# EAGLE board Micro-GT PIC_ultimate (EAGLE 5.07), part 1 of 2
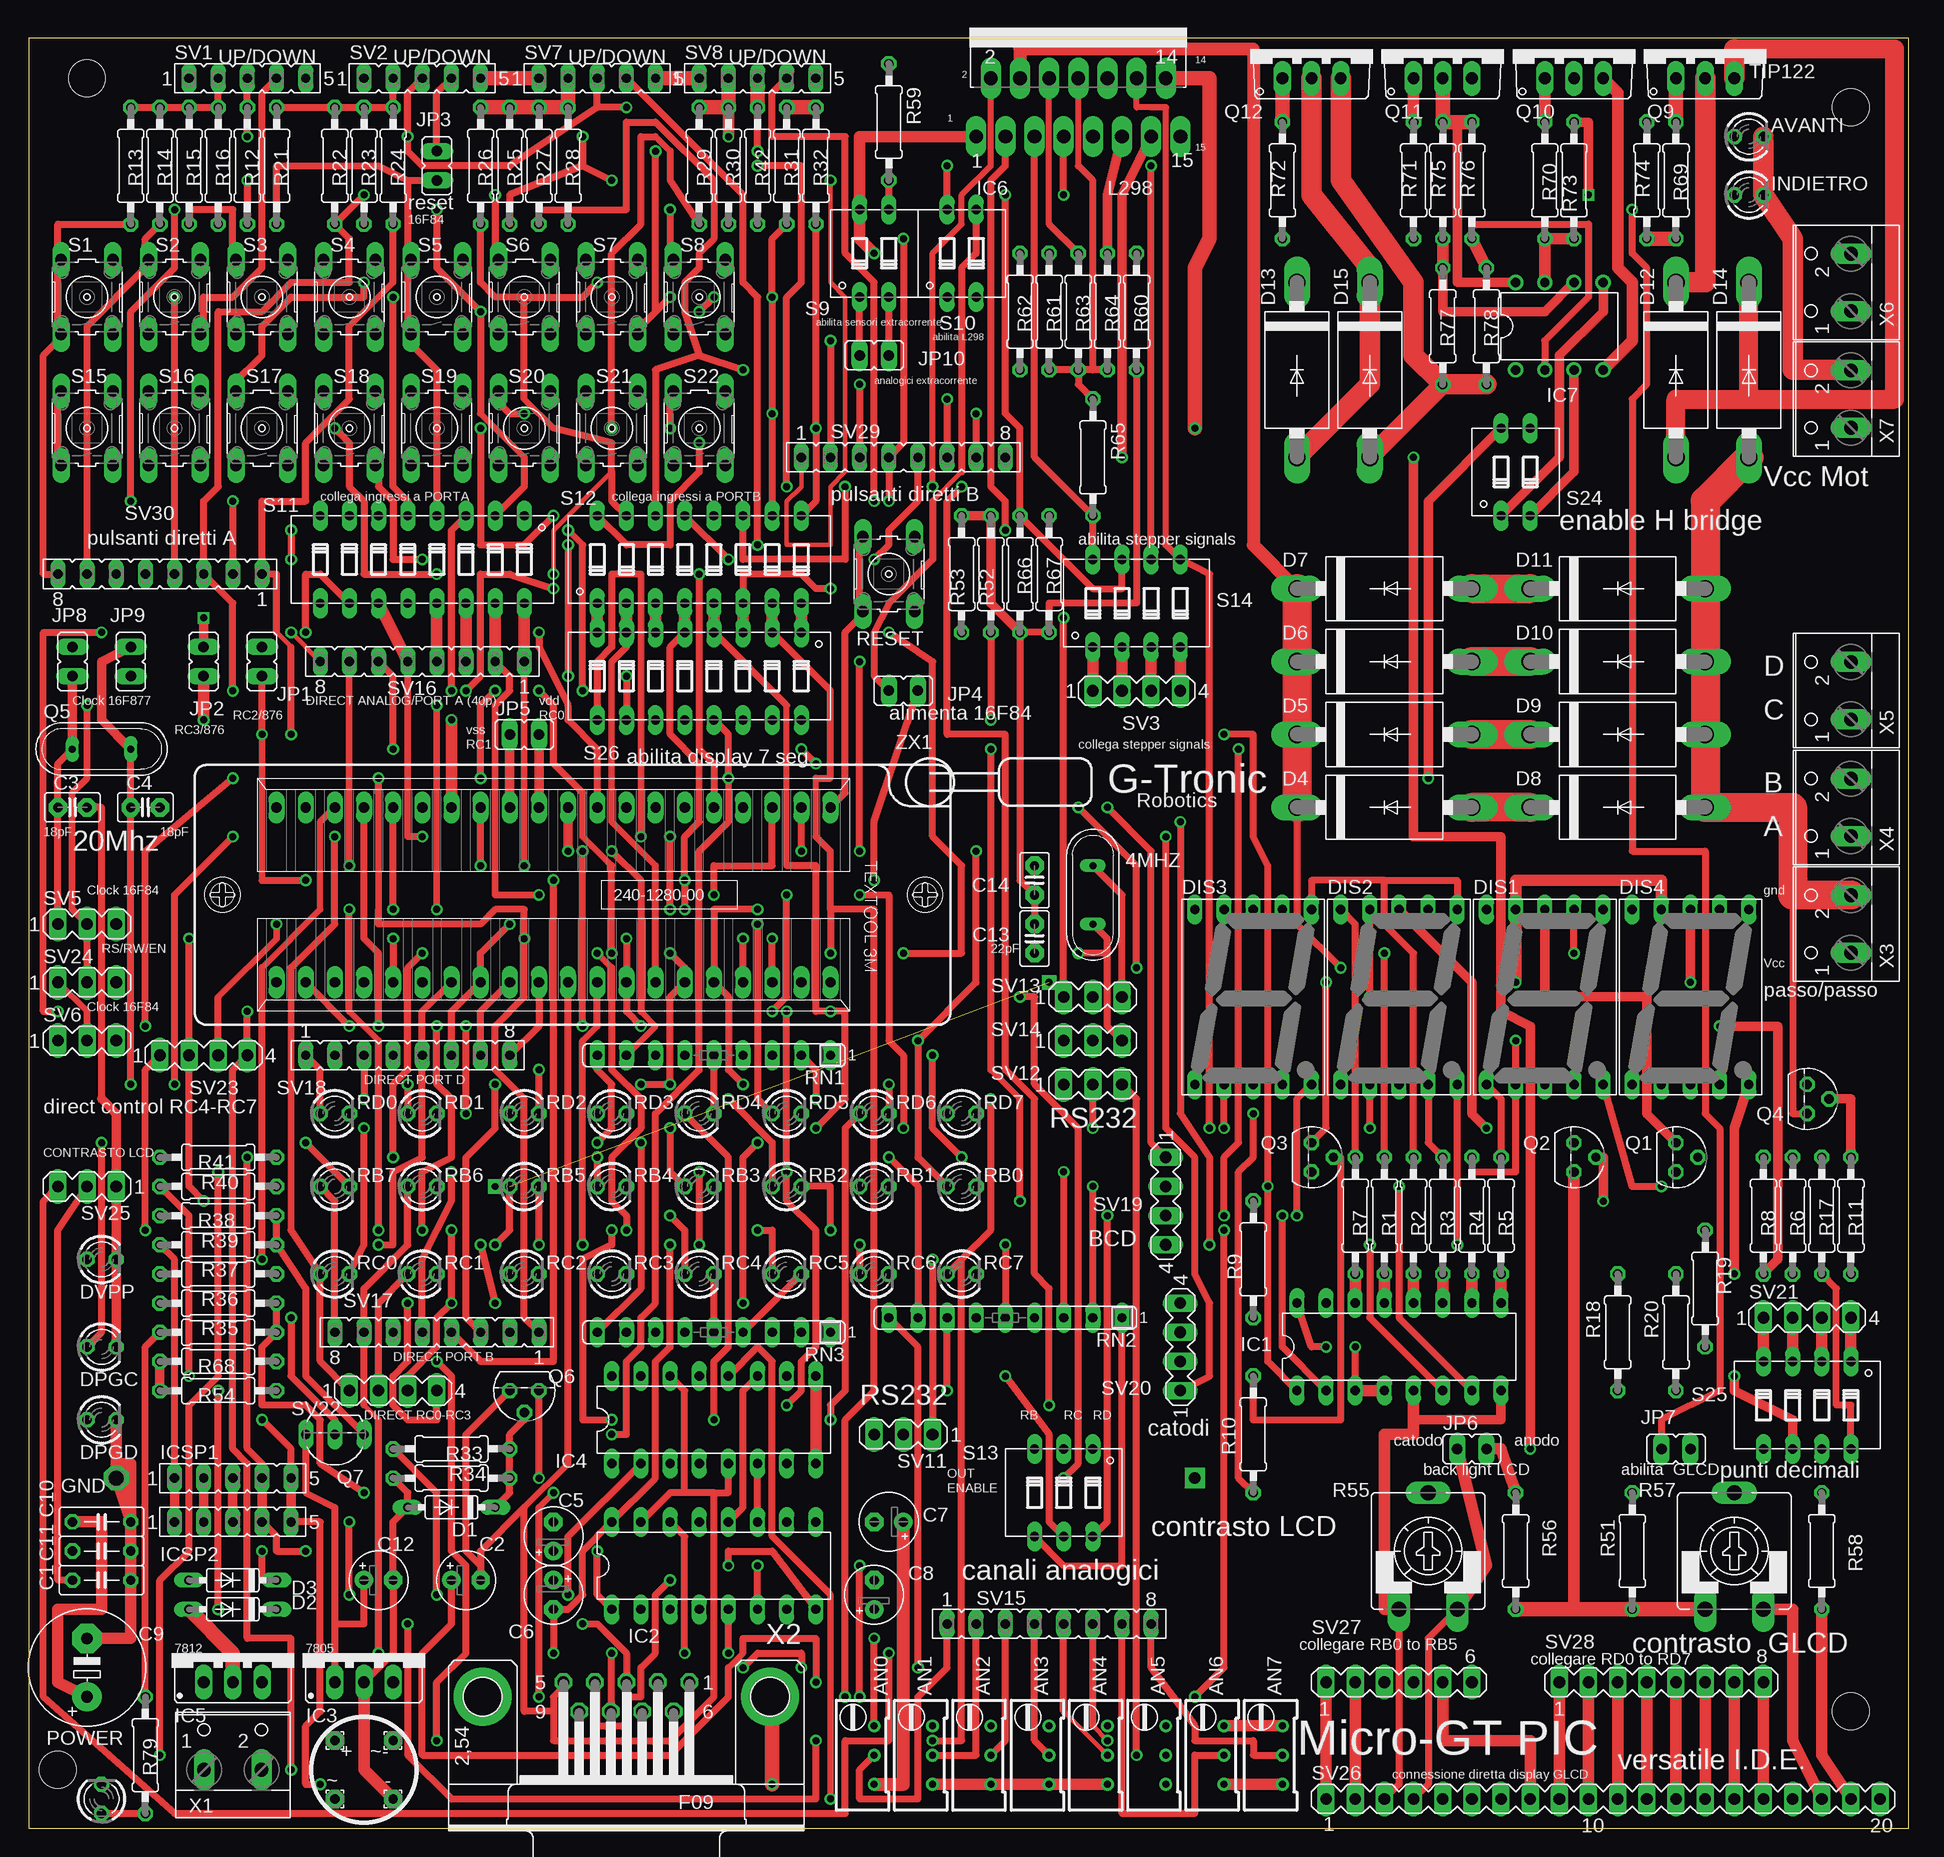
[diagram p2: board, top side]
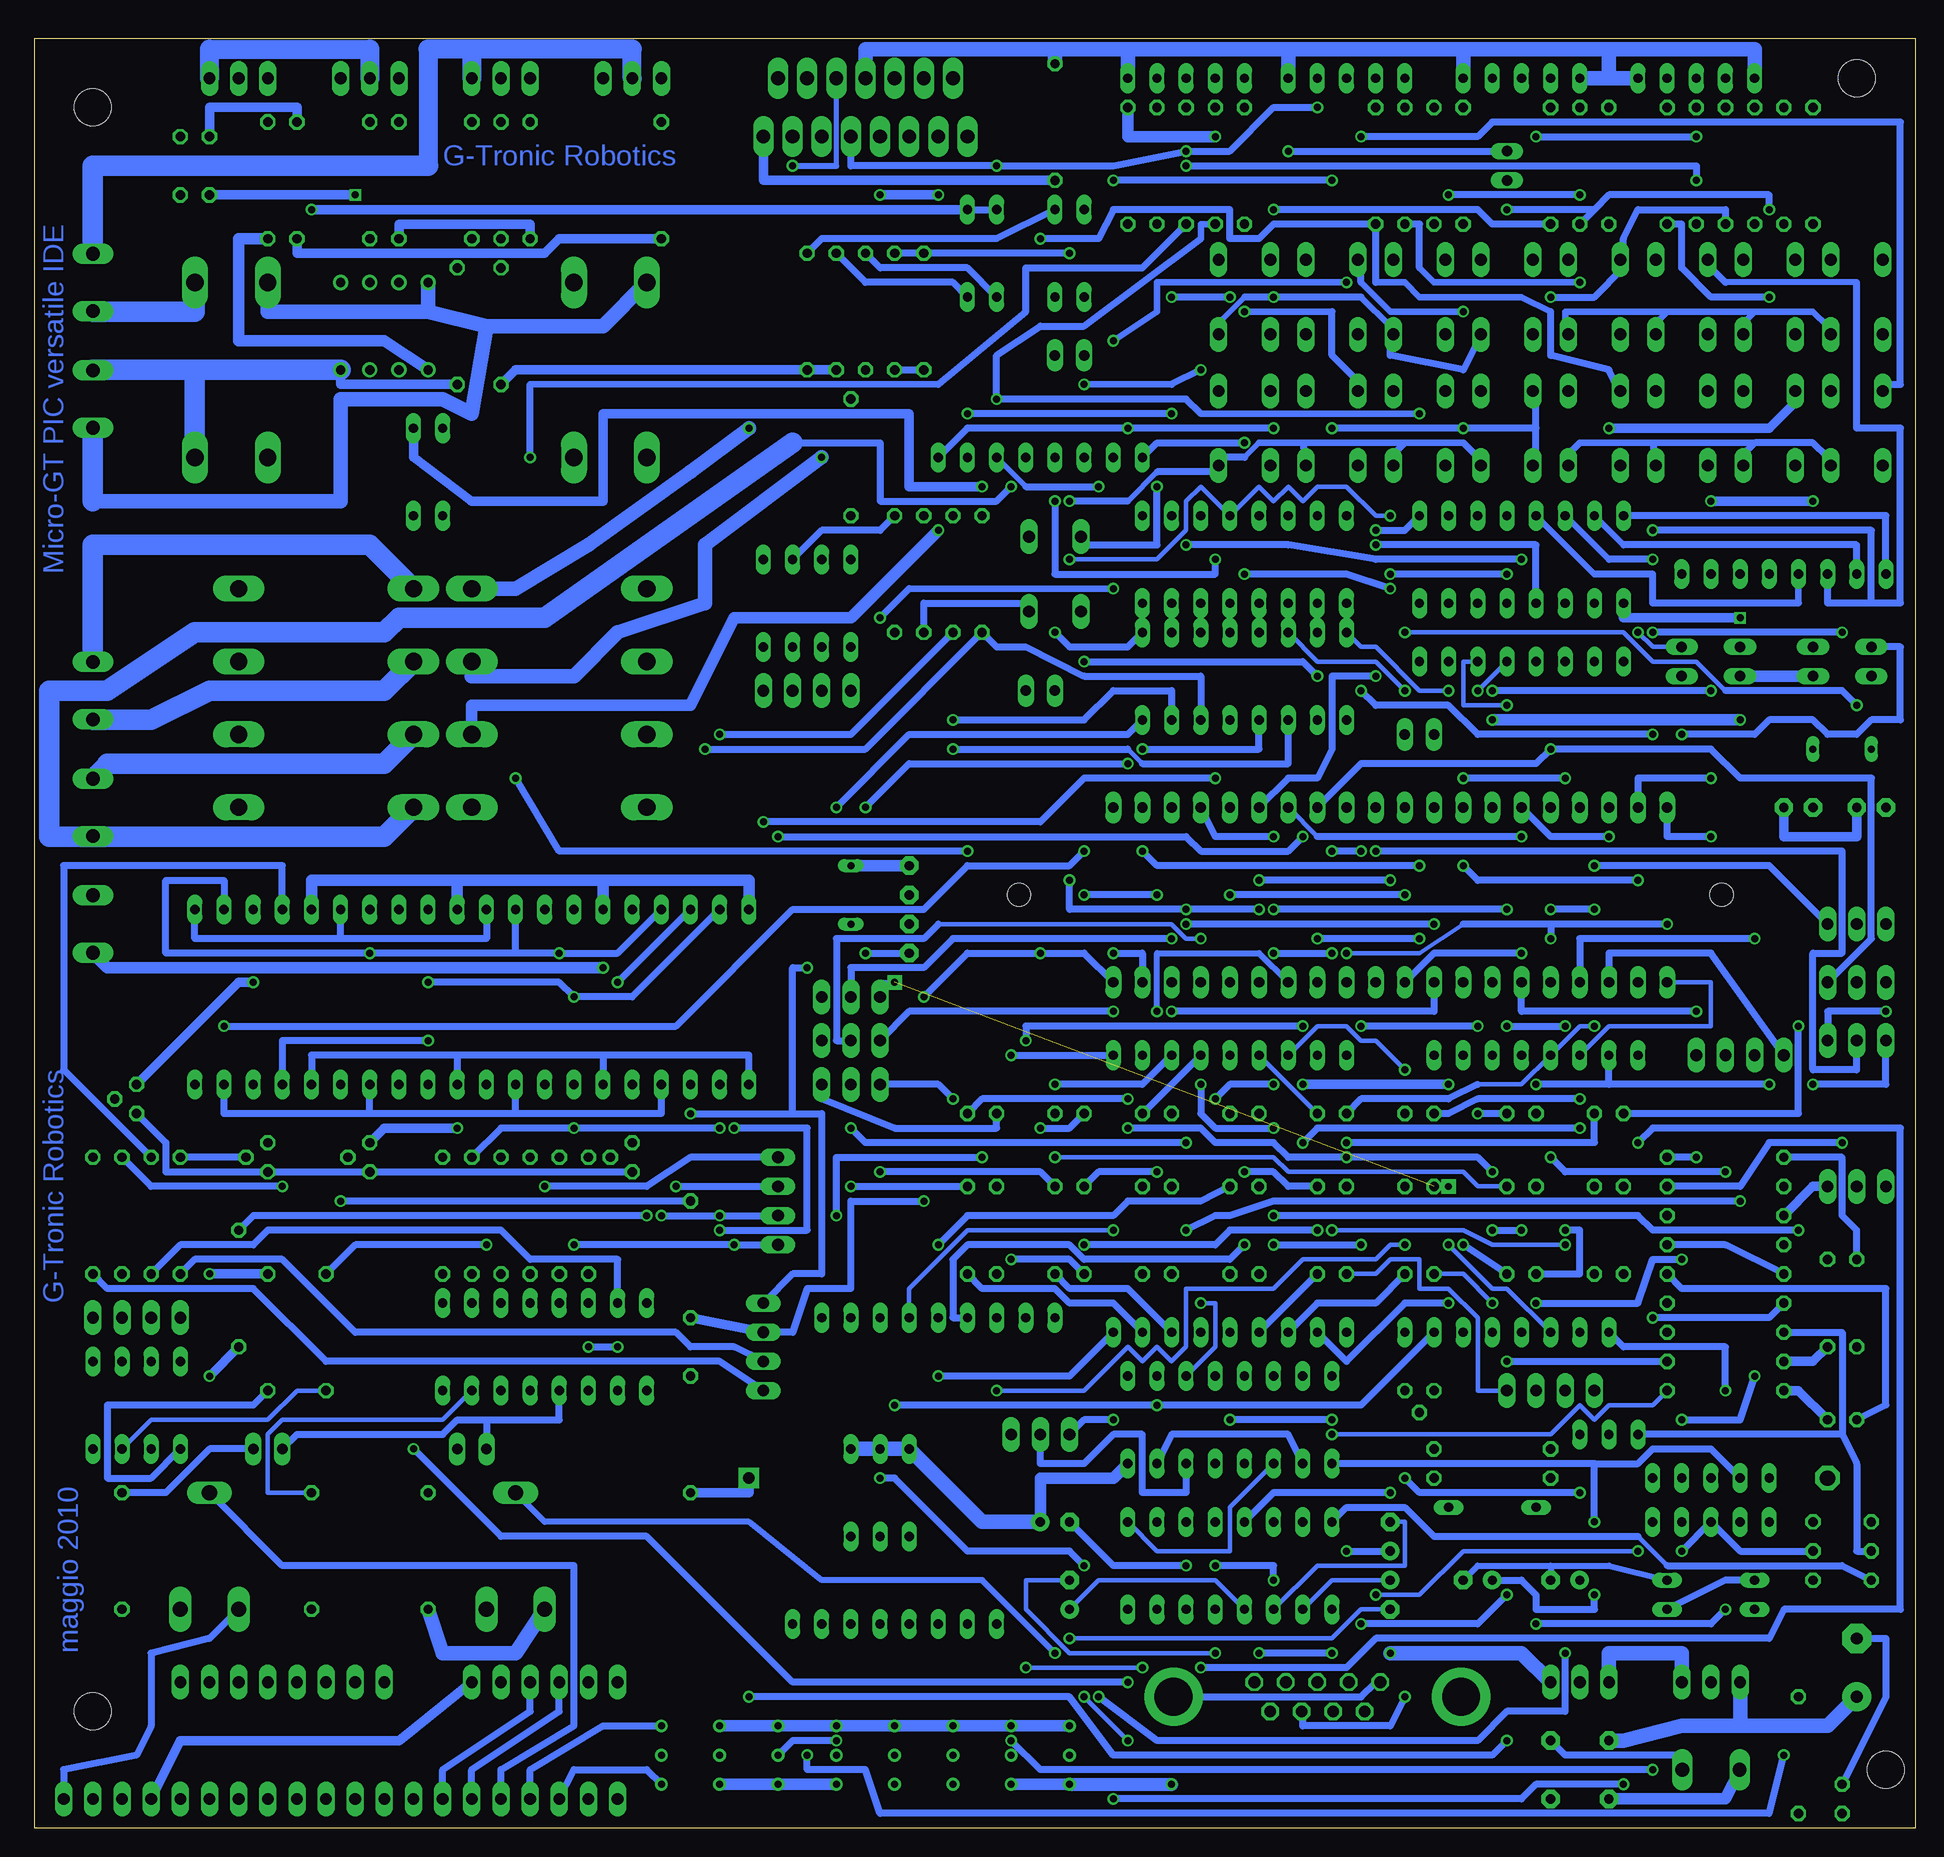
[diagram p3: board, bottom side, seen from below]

Size 163.81 x 155.88 mm. Coordinates in mm from the lower left corner, seen from the top.
Outline: 0,0 163.81,0 163.81,155.88 0,155.88 0,0
Copper layers (1*16): Top 0.035mm / dielectric 1.5mm / Bottom 0.035mm
Design rules "default": minimum track width 10mil, minimum drill 24mil, track to track 8mil, track to pad 8mil, pad to pad 8mil, via to via 8mil, smd to smd 8mil, copper to edge 40mil, drill to drill 8mil, minimum pad ring 10mil, minimum via ring 8mil, stop-mask expansion 4mil, vias tented up to drill 0mil, thermal gap 10mil
Holes 3.2 mm at 158.75,149.86 158.75,10.16 2.54,5.08 5.08,152.4

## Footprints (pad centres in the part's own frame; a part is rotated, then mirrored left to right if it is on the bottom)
QS = drill 0.61 long: 1 -2.54,0; 2 2.54,0
1,6/0,8 = drill 0.813 pad 1.6 octagon: 1 0,0
RTRIM64W = drill 0.61 round: 1 1.27,-2.54; 2 1.27,0; 3 1.27,2.54
LED3MM = drill 0.813 octagon: A -1.27,0; K 1.27,0
C050-025X075 = drill 0.813 octagon: 1 -2.54,0; 2 2.54,0
E2,5-5 = drill 0.813 pad 1.6 round: + -1.27,0 | drill 0.813 pad 1.6 octagon: - 1.27,0
C2.5-2 = drill 0.813 pad 1.6 octagon: 1 -1.27,0; 2 1.27,0
E5-10,5 = drill 1.016 pad 2.54 round: + -2.54,0 | drill 1.016 pad 2.54 octagon: - 2.54,0
DO35-7 = drill 0.813 long: A 3.81,0; C -3.81,0
DO201-15 = drill 1.499 long: A 7.62,0; C -7.62,0
HDSP-M = drill 0.813 long: 1 -5.08,-7.62; 2 -2.54,-7.62; 3 0,-7.62; 4 2.54,-7.62; 5 5.08,-7.62; 6 5.08,7.62; 7 2.54,7.62; 8 0,7.62; 9 -2.54,7.62; 10 -5.08,7.62
P1-13 = drill 1.321 pad 2.159 octagon: TP 0,0
DIL16 = drill 0.813 long: 1 -8.89,-3.81; 2 -6.35,-3.81; 3 -3.81,-3.81; 4 -1.27,-3.81; 5 1.27,-3.81; 6 3.81,-3.81; 7 6.35,-3.81; 8 8.89,-3.81; 9 8.89,3.81; 10 6.35,3.81; 11 3.81,3.81; 12 1.27,3.81; 13 -1.27,3.81; 14 -3.81,3.81; 15 -6.35,3.81; 16 -8.89,3.81
78XXS = drill 1.016 long: GND 0,-2.54; IN -2.54,-2.54; OUT 2.54,-2.54
MULTIWATT-15 = drill 1.2 long: 1 -8.89,-7.62; 2 -7.62,-2.54; 3 -6.35,-7.62; 4 -5.08,-2.54; 5 -3.81,-7.62; 6 -2.54,-2.54; 7 -1.27,-7.62; 8 0,-2.54; 9 1.27,-7.62; 10 2.54,-2.54; 11 3.81,-7.62; 12 5.08,-2.54; 13 6.35,-7.62; 14 7.62,-2.54; 15 8.89,-7.62
DIL08 = drill 0.813 pad 1.27 round: 1 -3.81,-3.81; 2 -1.27,-3.81; 3 1.27,-3.81; 4 3.81,-3.81; 5 3.81,3.81; 6 1.27,3.81; 7 -1.27,3.81; 8 -3.81,3.81
FE05-1 = drill 0.813 long: 1 -5.08,0; 2 -2.54,0; 3 0,0; 4 2.54,0; 5 5.08,0
JP1 = drill 0.914 long: 1 0,-1.27; 2 0,1.27
TO92 = drill 0.813 octagon: 1 1.27,0; 2 0,1.905; 3 -1.27,0
TO92-EBC = drill 0.813 long: B 0,-1.27; C -2.54,-1.27; E 2.54,-1.27
TO220AV = drill 1.016 long: B -2.54,-2.54; C 0,-2.54; E 2.54,-2.54
0207/10 = drill 0.813 octagon: 1 -5.08,0; 2 5.08,0
CA9V = drill 1.321 long: A -2.54,-5.08; E 2.54,-5.08; S 0,5.08
B3F-10XX = drill 1.016 long: 1 -3.251,2.261; 2 3.251,2.261; 3 -3.251,-2.261; 4 3.251,-2.261
SIL9 = drill 0.813 long: 1 -10.16,0; 2 -7.62,0; 3 -5.08,0; 4 -2.54,0; 5 0,0; 6 2.54,0; 7 5.08,0; 8 7.62,0; 9 10.16,0
DIP02YL = drill 0.813 long: 1 -1.27,-3.81; 2 1.27,-3.81; 3 1.27,3.81; 4 -1.27,3.81
DIP08YL = drill 0.813 long: 1 -8.89,-3.81; 2 -6.35,-3.81; 3 -3.81,-3.81; 4 -1.27,-3.81; 5 1.27,-3.81; 6 3.81,-3.81; 7 6.35,-3.81; 8 8.89,-3.81; 9 8.89,3.81; 10 6.35,3.81; 11 3.81,3.81; 12 1.27,3.81; 13 -1.27,3.81; 14 -3.81,3.81; 15 -6.35,3.81; 16 -8.89,3.81
DIP03YL = drill 0.813 long: 1 -2.54,-3.81; 2 0,-3.81; 3 2.54,-3.81; 4 2.54,3.81; 5 0,3.81; 6 -2.54,3.81
DIP04YL = drill 0.813 long: 1 -3.81,-3.81; 2 -1.27,-3.81; 3 1.27,-3.81; 4 3.81,-3.81; 5 3.81,3.81; 6 1.27,3.81; 7 -1.27,3.81; 8 -3.81,3.81
MA04-1 = drill 1.016 long: 1 -3.81,0; 2 -1.27,0; 3 1.27,0; 4 3.81,0
MA03-1 = drill 1.016 long: 1 -2.54,0; 2 0,0; 3 2.54,0
FE08 = drill 0.813 long: 1 -8.89,0; 2 -6.35,0; 3 -3.81,0; 4 -1.27,0; 5 1.27,0; 6 3.81,0; 7 6.35,0; 8 8.89,0
MA20-1 = drill 1.016 long: 1 -24.13,0; 2 -21.59,0; 3 -19.05,0; 4 -16.51,0; 5 -13.97,0; 6 -11.43,0; 7 -8.89,0; 8 -6.35,0; 9 -3.81,0; 10 -1.27,0; 11 1.27,0; 12 3.81,0; 13 6.35,0; 14 8.89,0; 15 11.43,0; 16 13.97,0; 17 16.51,0; 18 19.05,0; 19 21.59,0; 20 24.13,0
MA06-1 = drill 1.016 long: 1 -6.35,0; 2 -3.81,0; 3 -1.27,0; 4 1.27,0; 5 3.81,0; 6 6.35,0
MA08-1 = drill 1.016 long: 1 -8.89,0; 2 -6.35,0; 3 -3.81,0; 4 -1.27,0; 5 1.27,0; 6 3.81,0; 7 6.35,0; 8 8.89,0
W237-102 = drill 1.194 long: 1 -2.5,-1.27; 2 2.5,-1.27
F09HP = drill 1.016 octagon: 1 -5.486,-1.27; 2 -2.743,-1.27; 3 0,-1.27; 4 2.743,-1.27; 5 5.486,-1.27; 6 -4.115,1.27; 7 -1.372,1.27; 8 1.372,1.27; 9 4.115,1.27 | drill 3.302 pad 5.08 round: G1 -12.522,0; G2 12.522,0
240-1280-00-0602J = drill 0.9 long: 1 -24.13,-7.62; 2 -21.59,-7.62; 3 -19.05,-7.62; 4 -16.51,-7.62; 5 -13.97,-7.62; 6 -11.43,-7.62; 7 -8.89,-7.62; 8 -6.35,-7.62; 9 -3.81,-7.62; 10 -1.27,-7.62; 11 1.27,-7.62; 12 3.81,-7.62; 13 6.35,-7.62; 14 8.89,-7.62; 15 11.43,-7.62; 16 13.97,-7.62; 17 16.51,-7.62; 18 19.05,-7.62; 19 21.59,-7.62; 20 24.13,-7.62; 21 24.13,7.62; 22 21.59,7.62; 23 19.05,7.62; 24 16.51,7.62; 25 13.97,7.62; 26 11.43,7.62; 27 8.89,7.62; 28 6.35,7.62; 29 3.81,7.62; 30 1.27,7.62; 31 -1.27,7.62; 32 -3.81,7.62; 33 -6.35,7.62; 34 -8.89,7.62; 35 -11.43,7.62; 36 -13.97,7.62; 37 -16.51,7.62; 38 -19.05,7.62; 39 -21.59,7.62; 40 -24.13,7.62 | hole 2: 28.86,0; -32.36,0

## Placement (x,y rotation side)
4MHZ  [QS]  92.71,81.28 90 top
+  [1,6/0,8]  26.67,7.62 0 top
-  [1,6/0,8]  31.75,2.54 0 top
AN0  [RTRIM64W]  72.39,6.35 0 top
AN1  [RTRIM64W]  77.47,6.35 0 top
AN2  [RTRIM64W]  82.55,6.35 0 top
AN3  [RTRIM64W]  87.63,6.35 0 top
AN4  [RTRIM64W]  92.71,6.35 0 top
AN5  [RTRIM64W]  97.79,6.35 0 top
AN6  [RTRIM64W]  102.87,6.35 0 top
AN7  [RTRIM64W]  107.95,6.35 0 top
AVANTI  [LED3MM]  149.86,147.32 0 top
C1  [C050-025X075]  6.35,21.59 0 top
C2  [E2,5-5]  38.1,21.59 0 top
C3  [C2.5-2]  3.81,88.9 0 top
C4  [C2.5-2]  10.16,88.9 0 top
C5  [E2,5-5]  45.72,25.4 90 top
C6  [E2,5-5]  45.72,20.32 270 top
C7  [E2,5-5]  74.93,26.67 180 top
C8  [E2,5-5]  73.66,20.32 90 top
C9  [E5-10,5]  5.08,13.97 90 top
C10  [C050-025X075]  6.35,26.67 0 top
C11  [C050-025X075]  6.35,24.13 0 top
C12  [E2,5-5]  30.48,21.59 0 top
C13  [C2.5-2]  87.63,77.47 90 top
C14  [C2.5-2]  87.63,82.55 270 top
D1  1N4148  [DO35-7]  36.83,27.94 180 top
D2  1N4148  [DO35-7]  17.78,19.05 180 top
D3  1N4148  [DO35-7]  17.78,21.59 180 top
D4  GI852  [DO201-15]  118.11,88.9 0 top
D5  GI852  [DO201-15]  118.11,95.25 0 top
D6  GI852  [DO201-15]  118.11,101.6 0 top
D7  GI852  [DO201-15]  118.11,107.95 0 top
D8  GI852  [DO201-15]  138.43,88.9 0 top
D9  GI852  [DO201-15]  138.43,95.25 0 top
D10  GI852  [DO201-15]  138.43,101.6 0 top
D11  GI852  [DO201-15]  138.43,107.95 0 top
D12  GI852  [DO201-15]  143.51,127 270 top
D13  GI852  [DO201-15]  110.49,127 270 top
D14  GI852  [DO201-15]  149.86,127 270 top
D15  GI852  [DO201-15]  116.84,127 270 top
DIS1  HD-H103  [HDSP-M]  132.08,72.39 0 top
DIS2  HD-H103  [HDSP-M]  119.38,72.39 0 top
DIS3  HD-H103  [HDSP-M]  106.68,72.39 0 top
DIS4  HD-H103  [HDSP-M]  144.78,72.39 0 top
DPGC  [LED3MM]  6.35,41.91 0 top
DPGD  [LED3MM]  6.35,35.56 0 top
DVPP  [LED3MM]  6.35,49.53 0 top
GND  TPSPAD1-13  [P1-13]  7.62,30.48 0 top
IC1  4511N  [DIL16]  119.38,41.91 0 top
IC2  MAX232  [DIL16]  59.69,22.86 0 top
IC3  [78XXS]  29.21,15.24 0 top
IC4  4049N  [DIL16]  59.69,35.56 0 top
IC5  [78XXS]  17.78,15.24 0 top
IC6  L298  [MULTIWATT-15]  91.44,154.94 0 top
IC7  TL082P  [DIL08]  133.35,130.81 0 top
ICSP1  [FE05-1]  17.78,30.48 0 top
ICSP2  [FE05-1]  17.78,26.67 0 top
INDIETRO  [LED3MM]  149.86,142.24 0 top
JP1  [JP1]  20.32,101.6 180 top
JP2  [JP1]  15.24,101.6 180 top
JP3  [JP1]  35.56,144.78 0 top
JP4  [JP1]  76.2,99.06 270 top
JP5  [JP1]  43.18,95.25 270 top
JP6  [JP1]  125.73,33.02 270 top
JP7  [JP1]  143.51,33.02 90 top
JP8  [JP1]  3.81,101.6 0 top
JP9  [JP1]  8.89,101.6 0 top
JP10  [JP1]  73.66,128.27 270 top
POWER  [LED3MM]  6.35,2.54 90 top
Q1  BC337  [TO92]  143.51,58.42 270 top
Q2  BC337  [TO92]  134.62,58.42 270 top
Q3  BC337  [TO92]  111.76,58.42 270 top
Q4  BC337  [TO92]  154.94,63.5 270 top
Q5  [QS]  6.35,93.98 0 top
Q6  BC547  [TO92]  43.18,38.1 180 top
Q7  BC557C  [TO92-EBC]  26.67,33.02 180 top
Q9  TIP122  [TO220AV]  146.05,154.94 0 top
Q10  TIP122  [TO220AV]  134.62,154.94 0 top
Q11  TIP122  [TO220AV]  123.19,154.94 0 top
Q12  TIP122  [TO220AV]  111.76,154.94 0 top
R1  [0207/10]  118.11,53.34 90 top
R2  [0207/10]  120.65,53.34 90 top
R3  [0207/10]  123.19,53.34 90 top
R4  [0207/10]  125.73,53.34 90 top
R5  [0207/10]  128.27,53.34 90 top
R6  [0207/10]  153.67,53.34 90 top
R7  [0207/10]  115.57,53.34 90 top
R8  [0207/10]  151.13,53.34 90 top
R9  [0207/10]  106.68,49.53 270 top
R10  [0207/10]  106.68,34.29 90 top
R11  [0207/10]  158.75,53.34 90 top
R12  [0207/10]  19.05,144.78 90 top
R13  [0207/10]  8.89,144.78 90 top
R14  [0207/10]  11.43,144.78 90 top
R15  [0207/10]  13.97,144.78 90 top
R16  [0207/10]  16.51,144.78 90 top
R17  [0207/10]  156.21,53.34 90 top
R18  [0207/10]  138.43,43.18 90 top
R19  [0207/10]  146.05,46.99 90 top
R20  [0207/10]  143.51,43.18 90 top
R21  [0207/10]  21.59,144.78 90 top
R22  [0207/10]  26.67,144.78 90 top
R23  [0207/10]  29.21,144.78 90 top
R24  [0207/10]  31.75,144.78 90 top
R25  [0207/10]  41.91,144.78 90 top
R26  [0207/10]  39.37,144.78 90 top
R27  [0207/10]  44.45,144.78 90 top
R28  [0207/10]  46.99,144.78 90 top
R29  [0207/10]  58.42,144.78 90 top
R30  [0207/10]  60.96,144.78 90 top
R31  [0207/10]  66.04,144.78 90 top
R32  [0207/10]  68.58,144.78 90 top
R33  [0207/10]  36.83,33.02 0 top
R34  [0207/10]  36.83,30.48 180 top
R35  [0207/10]  16.51,43.18 180 top
R36  [0207/10]  16.51,45.72 180 top
R37  [0207/10]  16.51,48.26 180 top
R38  [0207/10]  16.51,53.34 0 top
R39  [0207/10]  16.51,50.8 180 top
R40  [0207/10]  16.51,55.88 180 top
R41  [0207/10]  16.51,58.42 0 top
R42  [0207/10]  63.5,144.78 90 top
R51  [0207/10]  139.7,24.13 90 top
R52  [0207/10]  83.82,109.22 270 top
R53  [0207/10]  81.28,109.22 270 top
R54  [0207/10]  16.51,38.1 0 top
R55  [CA9V]  121.92,24.13 0 top
R56  [0207/10]  129.54,24.13 90 top
R57  [CA9V]  148.59,24.13 0 top
R58  [0207/10]  156.21,24.13 90 top
R59  [0207/10]  74.93,148.59 270 top
R60  [0207/10]  96.52,132.08 90 top
R61  [0207/10]  88.9,132.08 90 top
R62  [0207/10]  86.36,132.08 90 top
R63  [0207/10]  91.44,132.08 90 top
R64  [0207/10]  93.98,132.08 90 top
R65  [0207/10]  92.71,119.38 270 top
R66  [0207/10]  86.36,109.22 90 top
R67  [0207/10]  88.9,109.22 90 top
R68  [0207/10]  16.51,40.64 0 top
R69  [0207/10]  143.51,143.51 90 top
R70  [0207/10]  132.08,143.51 90 top
R71  [0207/10]  120.65,143.51 270 top
R72  [0207/10]  109.22,143.51 270 top
R73  [0207/10]  134.62,143.51 270 top
R74  [0207/10]  140.97,143.51 270 top
R75  [0207/10]  123.19,143.51 270 top
R76  [0207/10]  125.73,143.51 270 top
R77  [0207/10]  123.19,130.81 90 top
R78  [0207/10]  127,130.81 90 top
R79  [0207/10]  10.16,6.35 90 top
RB0  [LED3MM]  81.28,55.88 0 top
RB1  [LED3MM]  73.66,55.88 0 top
RB2  [LED3MM]  66.04,55.88 0 top
RB3  [LED3MM]  58.42,55.88 0 top
RB4  [LED3MM]  50.8,55.88 0 top
RB5  [LED3MM]  43.18,55.88 0 top
RB6  [LED3MM]  34.29,55.88 0 top
RB7  [LED3MM]  26.67,55.88 0 top
RC0  [LED3MM]  26.67,48.26 0 top
RC1  [LED3MM]  34.29,48.26 0 top
RC2  [LED3MM]  43.18,48.26 0 top
RC3  [LED3MM]  50.8,48.26 0 top
RC4  [LED3MM]  58.42,48.26 0 top
RC5  [LED3MM]  66.04,48.26 0 top
RC6  [LED3MM]  73.66,48.26 0 top
RC7  [LED3MM]  81.28,48.26 0 top
RD0  [LED3MM]  26.67,62.23 0 top
RD1  [LED3MM]  34.29,62.23 0 top
RD2  [LED3MM]  43.18,62.23 0 top
RD3  [LED3MM]  50.8,62.23 0 top
RD4  [LED3MM]  58.42,62.23 0 top
RD5  [LED3MM]  66.04,62.23 0 top
RD6  [LED3MM]  73.66,62.23 0 top
RD7  [LED3MM]  81.28,62.23 0 top
RESET  [B3F-10XX]  74.93,109.22 90 top
RN1  [SIL9]  59.69,67.31 180 top
RN2  [SIL9]  85.09,44.45 180 top
RN3  [SIL9]  59.69,43.18 180 top
S1  [B3F-10XX]  5.08,133.35 90 top
S2  [B3F-10XX]  12.7,133.35 90 top
S3  [B3F-10XX]  20.32,133.35 90 top
S4  [B3F-10XX]  27.94,133.35 90 top
S5  [B3F-10XX]  35.56,133.35 90 top
S6  [B3F-10XX]  43.18,133.35 90 top
S7  [B3F-10XX]  50.8,133.35 90 top
S8  [B3F-10XX]  58.42,133.35 90 top
S9  [DIP02YL]  73.66,137.16 0 top
S10  [DIP02YL]  81.28,137.16 0 top
S11  [DIP08YL]  34.29,110.49 180 top
S12  [DIP08YL]  58.42,110.49 0 top
S13  [DIP03YL]  90.17,29.21 180 top
S14  [DIP04YL]  96.52,106.68 0 top
S15  [B3F-10XX]  5.08,121.92 90 top
S16  [B3F-10XX]  12.7,121.92 90 top
S17  [B3F-10XX]  20.32,121.92 90 top
S18  [B3F-10XX]  27.94,121.92 90 top
S19  [B3F-10XX]  35.56,121.92 90 top
S20  [B3F-10XX]  43.18,121.92 90 top
S21  [B3F-10XX]  50.8,121.92 90 top
S22  [B3F-10XX]  58.42,121.92 90 top
S24  [DIP02YL]  129.54,118.11 0 top
S25  [DIP04YL]  154.94,36.83 180 top
S26  [DIP08YL]  58.42,100.33 180 top
SV1  [FE05-1]  19.05,152.4 0 top
SV2  [FE05-1]  34.29,152.4 0 top
SV3  [MA04-1]  96.52,99.06 0 top
SV5  [MA03-1]  5.08,78.74 0 top
SV6  [MA03-1]  5.08,68.58 0 top
SV7  [FE05-1]  49.53,152.4 0 top
SV8  [FE05-1]  63.5,152.4 0 top
SV11  [MA03-1]  76.2,34.29 180 top
SV12  [MA03-1]  92.71,64.77 0 top
SV13  [MA03-1]  92.71,72.39 0 top
SV14  [MA03-1]  92.71,68.58 0 top
SV15  [FE08]  88.9,17.78 0 top
SV16  [FE08]  34.29,101.6 180 top
SV17  [FE08]  35.56,43.18 180 top
SV18  [FE08]  33.02,67.31 0 top
SV19  [MA04-1]  99.06,54.61 270 top
SV20  [MA04-1]  100.33,41.91 90 top
SV21  [MA04-1]  154.94,44.45 0 top
SV22  [MA04-1]  31.75,38.1 0 top
SV23  [MA04-1]  15.24,67.31 0 top
SV24  [MA03-1]  5.08,73.66 0 top
SV25  [MA03-1]  5.08,55.88 180 top
SV26  [MA20-1]  137.16,2.54 0 top
SV27  [MA06-1]  119.38,12.7 0 top
SV28  [MA08-1]  142.24,12.7 0 top
SV29  [FE08]  76.2,119.38 0 top
SV30  [FE08]  11.43,109.22 180 top
X1  [W237-102]  17.78,6.35 0 top
X2  [F09HP]  52.07,11.43 180 top
X3  [W237-102]  157.48,78.74 90 top
X4  [W237-102]  157.48,88.9 90 top
X5  [W237-102]  157.48,99.06 90 top
X6  [W237-102]  157.48,134.62 90 top
X7  [W237-102]  157.48,124.46 90 top
ZX1  240-1280-00-0602J  [240-1280-00-0602J]  45.72,81.28 180 top
~  [1,6/0,8]  26.67,2.54 0 top
~-  [1,6/0,8]  31.75,7.62 0 top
